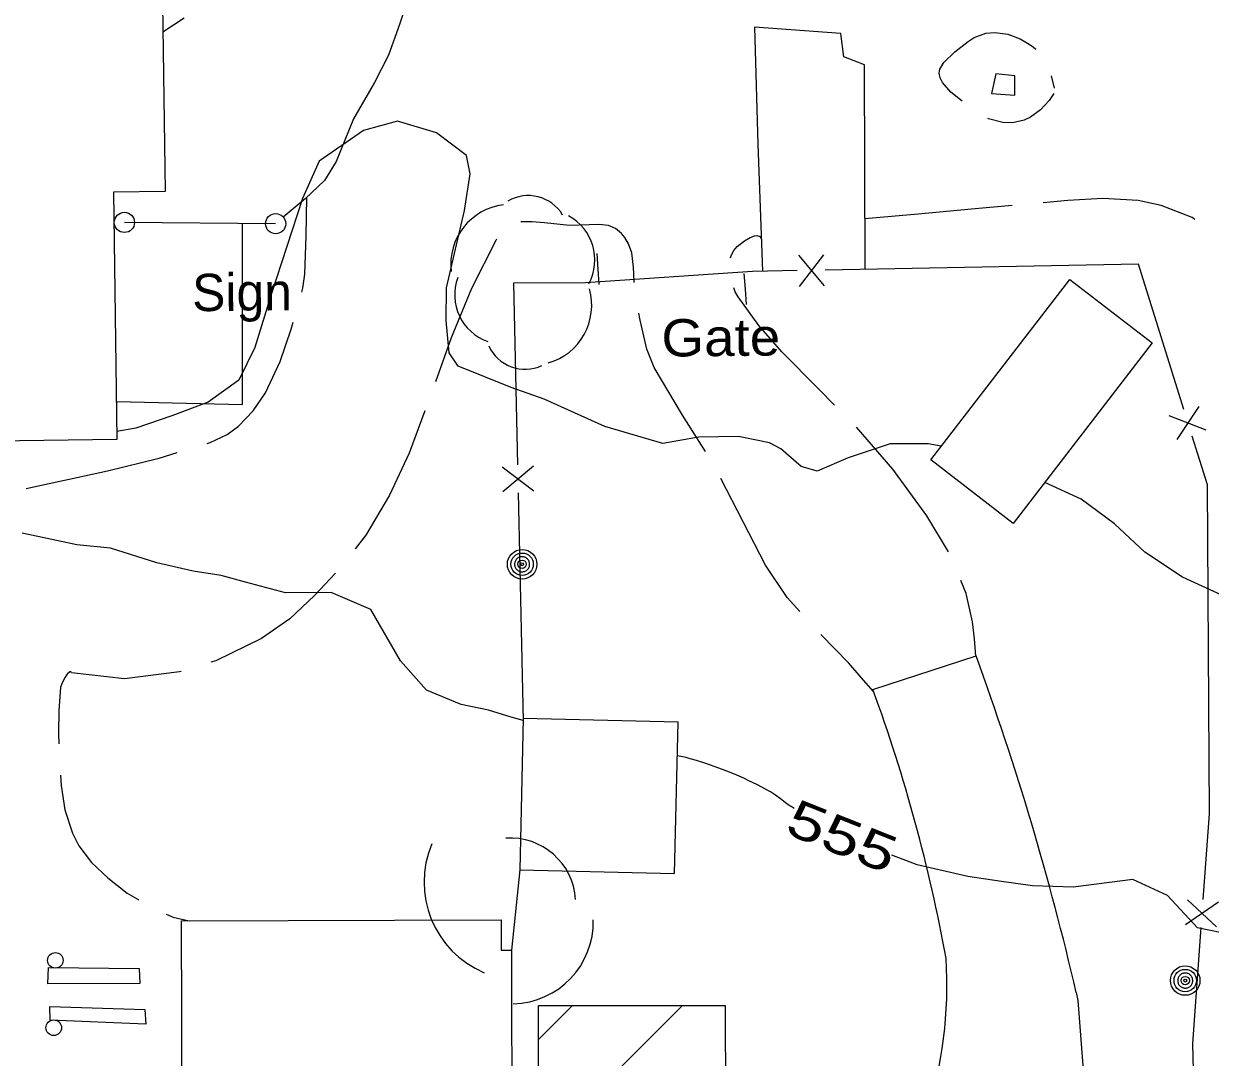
# Model space of a CAD drawing. Extents: x 2361284 to 2366480, y 6976556 to 6985346.
# Drawn here: x 2364468 to 2364620.8, y 6980286.6 to 6980419.7 of the extents above; entities that cross this region are included whole.
import ezdxf
from ezdxf.enums import TextEntityAlignment as Align

# ---------------------------------------------------------------- set-up
doc = ezdxf.new("R2010")
doc.units = 0
doc.header["$LTSCALE"] = 1.9
for name, color, linetype, lineweight in [('10', 7, 'Continuous', 13), ('11', 7, 'Continuous', 13), ('12', 7, 'Continuous', 13), ('13', 7, 'Continuous', 13), ('15', 7, 'Continuous', 13), ('16', 7, 'Continuous', 13), ('3', 7, 'Continuous', 13), ('4', 7, 'Continuous', 13), ('5', 7, 'Continuous', 13), ('7', 7, 'Continuous', 13), ('9', 7, 'Continuous', 13)]:
    doc.layers.add(name, color=color, linetype=linetype, lineweight=lineweight)

msp = doc.modelspace()

# ---------------------------------------------------------------- linework, layer by layer
at = {"layer": '10'}
for points in [[(2364595.653, 6980412.994), (2364593.181, 6980413.281), (2364592.655, 6980410.735), (2364595.627, 6980410.504)], [(2364482.84, 6980298.035), (2364482.919, 6980296.086), (2364471.079, 6980296.063), (2364471.179, 6980298.154)], [(2364483.571, 6980292.752), (2364483.709, 6980290.853), (2364471.373, 6980291.356), (2364471.336, 6980293.146)]]:
    msp.add_lwpolyline(points, close=True, dxfattribs=at)
at = {"layer": '11'}
msp.add_line((2364500.42, 6980393.958), (2364480.937, 6980394.123), dxfattribs=at)
for centre in [(2364480.938, 6980394.124), (2364500.421, 6980393.959)]:
    msp.add_circle(centre, 1.3, dxfattribs=at)
at = {"layer": '12'}
for points in [[(2364532.31, 6980329.987), (2364530.766, 6980330.412), (2364527.847, 6980331.325), (2364524.33, 6980332.021), (2364519.861, 6980333.9), (2364516.495, 6980337.638), (2364512.672, 6980344.282), (2364507.561, 6980346.443), (2364501.682, 6980346.437), (2364496.558, 6980347.788), (2364493.39, 6980348.638), (2364489.774, 6980349.224), (2364485.134, 6980350.269), (2364479.135, 6980352.183), (2364474.801, 6980352.611), (2364467.767, 6980354.095)], [(2364567.209, 6980318.648), (2364566.831, 6980318.88), (2364566.584, 6980319.044), (2364566.102, 6980319.387), (2364565.627, 6980319.741), (2364564.993, 6980320.213), (2364564.67, 6980320.442), (2364564.173, 6980320.766), (2364563.917, 6980320.917), (2364563.056, 6980321.388), (2364562.476, 6980321.689), (2364561.306, 6980322.262), (2364560.715, 6980322.534), (2364559.521, 6980323.053), (2364558.313, 6980323.541), (2364557.499, 6980323.851), (2364555.854, 6980324.441), (2364555.45, 6980324.577), (2364554.642, 6980324.828), (2364553.829, 6980325.053), (2364553.283, 6980325.191), (2364552.174, 6980325.436)], [(2364623.777, 6980302.325), (2364619.168, 6980303.252), (2364615.319, 6980307.415), (2364610.849, 6980309.503), (2364603.177, 6980308.52), (2364597.935, 6980308.67), (2364593.91, 6980309.252), (2364589.605, 6980309.861), (2364583.039, 6980311.4), (2364579.807, 6980312.629)]]:
    msp.add_lwpolyline(points, dxfattribs=at)
at = {"layer": '13'}
for points in [[(2364485.894, 6980418.671), (2364488.627, 6980420.467)], [(2364586.167, 6980365.302), (2364584.493, 6980365.616), (2364579.573, 6980365.619), (2364574.15, 6980363.807), (2364570.166, 6980362.099), (2364568.125, 6980362.679), (2364565.483, 6980364.97), (2364564.05, 6980365.731), (2364560.024, 6980366.533), (2364554.894, 6980366.464), (2364550.282, 6980365.631), (2364542.839, 6980367.84), (2364535.026, 6980371.346), (2364530.762, 6980372.855), (2364523.946, 6980375.62), (2364522.768, 6980377.335), (2364522.4, 6980381.506), (2364522.45, 6980385.707), (2364524.765, 6980395.649), (2364525.478, 6980400.39), (2364524.988, 6980402.732), (2364521.12, 6980405.645), (2364516.124, 6980407.178), (2364511.725, 6980405.976), (2364506.013, 6980401.991), (2364503.859, 6980397.211), (2364499.837, 6980384.832), (2364497.731, 6980378.011), (2364495.691, 6980373.811), (2364491.737, 6980370.994), (2364487.054, 6980369.2), (2364482.389, 6980367.645), (2364479.973, 6980367.212)], [(2364622.311, 6980346.104), (2364617.259, 6980348.426), (2364612.398, 6980351.67), (2364608.483, 6980355.303), (2364604.192, 6980358.473), (2364599.492, 6980360.628)]]:
    msp.add_lwpolyline(points, dxfattribs=at)
at = {"layer": '15'}
msp.add_line((2364600.304, 6980412.998), (2364600.699, 6980411.412), dxfattribs=at)
for points in [[(2364588.865, 6980409.749), (2364587.403, 6980410.906), (2364586.321, 6980412.125), (2364586.006, 6980412.732), (2364585.89, 6980413.341), (2364585.975, 6980413.852), (2364586.497, 6980414.737), (2364587.895, 6980416.08), (2364589.611, 6980417.417), (2364590.416, 6980417.945), (2364591.911, 6980418.479), (2364593.05, 6980418.59), (2364594.732, 6980418.366), (2364596.308, 6980417.771), (2364597.293, 6980417.23), (2364597.988, 6980416.756), (2364598.361, 6980416.42)], [(2364600.685, 6980410.712), (2364600.064, 6980409.806), (2364598.945, 6980408.625), (2364597.654, 6980407.693), (2364596.858, 6980407.305), (2364595.321, 6980406.971), (2364594.101, 6980406.989), (2364592.236, 6980407.471), (2364592.165, 6980407.511)], [(2364503.814, 6980385.12), (2364503.939, 6980385.641), (2364504.172, 6980387.443), (2364504.355, 6980392.385), (2364504.438, 6980397.336)], [(2364618.83, 6980394.514), (2364618.478, 6980394.75), (2364614.504, 6980396.313), (2364611.508, 6980396.934), (2364606.994, 6980397.191), (2364602.476, 6980396.938), (2364599.289, 6980396.648)], [(2364595.302, 6980396.29), (2364590.067, 6980395.82), (2364583.202, 6980395.205), (2364576.328, 6980394.6)], [(2364546.604, 6980386.397), (2364546.593, 6980386.526), (2364546.535, 6980388.366), (2364546.288, 6980390.204), (2364545.867, 6980391.35), (2364545.399, 6980392.165), (2364544.964, 6980392.711), (2364544.198, 6980393.354), (2364543.284, 6980393.715), (2364542.032, 6980393.843), (2364538.283, 6980393.708), (2364535.06, 6980394.057), (2364533.458, 6980394.212), (2364531.989, 6980394.218)], [(2364559.024, 6980389.575), (2364559.131, 6980389.966), (2364559.436, 6980390.519), (2364559.861, 6980391.003), (2364560.804, 6980391.772), (2364561.559, 6980392.199), (2364562.087, 6980392.384), (2364562.427, 6980392.427), (2364562.818, 6980392.311), (2364562.991, 6980391.933)], [(2364528.891, 6980391.948), (2364528.792, 6980391.797), (2364525.651, 6980385.597), (2364523.041, 6980379.262), (2364521.014, 6980373.592)], [(2364572.426, 6980370.591), (2364570.356, 6980372.682), (2364565.61, 6980377.467), (2364562.677, 6980380.849), (2364559.982, 6980384.534), (2364559.616, 6980385.18), (2364559.432, 6980385.678)], [(2364555.802, 6980364.603), (2364552.837, 6980369.285), (2364549.179, 6980375.43), (2364548.226, 6980377.812), (2364547.38, 6980381.544), (2364547.222, 6980382.442)], [(2364491.578, 6980365.642), (2364491.997, 6980365.766), (2364494.157, 6980366.817), (2364495.617, 6980367.881), (2364497.538, 6980369.849), (2364499.097, 6980372.154), (2364500.999, 6980376.191), (2364502.409, 6980380.366), (2364502.691, 6980381.279)], [(2364519.639, 6980369.839), (2364517.641, 6980364.42), (2364515.092, 6980359.006), (2364512.021, 6980353.825), (2364510.668, 6980352.062)], [(2364587.106, 6980351.699), (2364584.312, 6980356.344), (2364579.904, 6980362.332), (2364575.233, 6980367.738)], [(2364468.302, 6980359.841), (2364478.741, 6980362.15), (2364485.406, 6980363.764), (2364487.749, 6980364.476)], [(2364567.948, 6980343.998), (2364566.301, 6980345.811), (2364563.54, 6980349.985), (2364557.765, 6980361.122)], [(2364508.147, 6980348.958), (2364505.446, 6980346.052), (2364502.244, 6980343.083), (2364498.597, 6980340.538), (2364492.694, 6980337.672), (2364492.066, 6980337.476)], [(2364590.614, 6980338.273), (2364590.443, 6980340.491), (2364590.182, 6980342.699), (2364589.378, 6980346.31), (2364588.672, 6980348.024)], [(2364577.446, 6980333.717), (2364575.859, 6980335.532), (2364574.252, 6980337.337), (2364570.646, 6980341.043)], [(2364474.128, 6980336.095), (2364474.047, 6980336.264), (2364473.917, 6980336.253), (2364473.58, 6980335.93), (2364473.293, 6980335.537), (2364472.92, 6980334.834), (2364472.716, 6980334.212), (2364472.474, 6980331.248), (2364472.452, 6980328.278), (2364472.505, 6980326.948)], [(2364488.247, 6980336.289), (2364488.028, 6980336.227), (2364480.956, 6980335.33), (2364474.128, 6980336.095)], [(2364472.703, 6980322.95), (2364472.786, 6980321.581), (2364473.276, 6980318.485), (2364474.234, 6980315.455), (2364475.06, 6980313.813), (2364476.71, 6980311.679), (2364478.799, 6980309.707), (2364481.298, 6980307.731), (2364482.777, 6980306.855)], [(2364486.314, 6980305.009), (2364487.218, 6980304.657), (2364489.292, 6980304.177)]]:
    msp.add_lwpolyline(points, dxfattribs=at)
at = {"layer": '16'}
for centre, radius, start, end in [((2364532.968, 6980392.432), 5.15, 30.85983, 120.85983), ((2364530.699, 6980388.715), 7.729, 96.85071, 186.85071), ((2364535.097, 6980389.292), 6.444, 331.6668, 61.6668), ((2364529.933, 6980384.824), 6.444, 160.03592, 250.03592), ((2364533.409, 6980383.451), 7.729, 285.98261, 15.98261), ((2364532.561, 6980380.359), 5.15, 204.58182, 294.58182), ((2364530.637, 6980306.384), 8.449, 3.76416, 93.76416), ((2364532.22, 6980309.173), 12.681, 157.1296, 247.1296), ((2364530.769, 6980304.054), 10.572, 271.36296, 1.36296)]:
    msp.add_arc(centre, radius, start, end, dxfattribs=at)
at = {"layer": '3'}
for points in [[(2364524.216, 6980458.717), (2364523.72, 6980456.163), (2364522.845, 6980450.405), (2364521.533, 6980442.141), (2364519.439, 6980429.78), (2364517.678, 6980423.584), (2364516.386, 6980419.611), (2364514.944, 6980415.657), (2364513.137, 6980412.15), (2364510.461, 6980407.464), (2364508.213, 6980401.982), (2364506.727, 6980399.508), (2364504.24, 6980397.154), (2364501.392, 6980394.807)], [(2364576.35, 6980388.079), (2364576.279, 6980414.44), (2364573.609, 6980415.455), (2364573.221, 6980418.451), (2364562.091, 6980419.285), (2364562.525, 6980404.199), (2364563.15, 6980387.824)], [(2364479.916, 6980371.072), (2364496.15, 6980370.686), (2364496.139, 6980393.997)], [(2364577.364, 6980333.946), (2364577.364, 6980333.947), (2364590.644, 6980338.283), (2364590.644, 6980338.283)], [(2364603.556, 6980294.923), (2364603.766, 6980293.915), (2364606.46, 6980258.809), (2364597.591, 6980220.752), (2364582.102, 6980187.993), (2364563.55, 6980139.785), (2364555.874, 6980115.1), (2364550.217, 6980116.847), (2364550.217, 6980116.846)]]:
    msp.add_lwpolyline(points, dxfattribs=at)
for centre, radius, start, end in [((2364532.57, 6980295.02), 179.88, 21.07659, 62.51442), ((2364246.504, 6980212.191), 366.512, 13.04562, 20.12261), ((2364378.247, 6980261.13), 212.014, 10.3757, 20.08725), ((2364531.362, 6980295.938), 55.535, 342.16442, 3.48525)]:
    msp.add_arc(centre, radius, start, end, dxfattribs=at)
at = {"layer": '4'}
for centre, radius in [((2364532.169, 6980350.097), 1.9), ((2364532.169, 6980350.097), 1.442), ((2364532.169, 6980350.097), 0.539), ((2364532.169, 6980350.097), 0.192), ((2364472.043, 6980299.083), 1), ((2364617.593, 6980296.476), 1.9), ((2364617.593, 6980296.476), 1.442), ((2364617.593, 6980296.476), 0.539), ((2364617.593, 6980296.476), 0.192), ((2364471.835, 6980290.4), 1)]:
    msp.add_circle(centre, radius, dxfattribs=at)
for centre, start, end in [((2364532.169, 6980350.097), 174.71552, 185.96556), ((2364532.169, 6980350.097), 163.46611, 174.71615), ((2364532.169, 6980350.097), 185.96287, 197.21291), ((2364532.169, 6980350.097), 152.21535, 163.46538), ((2364532.169, 6980350.097), 197.21479, 208.46483), ((2364532.169, 6980350.097), 140.96646, 152.21649), ((2364532.169, 6980350.097), 208.46822, 219.71826), ((2364532.169, 6980350.097), 129.71376, 140.96379), ((2364532.169, 6980350.097), 118.46406, 129.71409), ((2364532.169, 6980350.097), 107.21593, 118.46597), ((2364532.169, 6980350.097), 95.96582, 107.21585), ((2364532.169, 6980350.097), 84.71553, 95.96557), ((2364532.169, 6980350.097), 73.46552, 84.71555), ((2364532.169, 6980350.097), 62.21535, 73.46538), ((2364532.169, 6980350.097), 50.96397, 62.214), ((2364532.169, 6980350.097), 39.71588, 50.96591), ((2364532.169, 6980350.097), 28.46656, 39.7166), ((2364532.169, 6980350.097), 320.96646, 332.21649), ((2364532.169, 6980350.097), 17.21479, 28.46483), ((2364532.169, 6980350.097), 332.21419, 343.46422), ((2364532.169, 6980350.097), 5.96345, 17.21348), ((2364532.169, 6980350.097), 343.46611, 354.71615), ((2364532.169, 6980350.097), 354.71553, 5.96557), ((2364532.169, 6980350.097), 219.71376, 230.96379), ((2364532.169, 6980350.097), 230.96397, 242.214), ((2364532.169, 6980350.097), 242.21812, 253.46815), ((2364532.169, 6980350.097), 253.46258, 264.71261), ((2364532.169, 6980350.097), 264.71553, 275.96557), ((2364532.169, 6980350.097), 275.96582, 287.21585), ((2364532.169, 6980350.097), 287.21593, 298.46597), ((2364532.169, 6980350.097), 298.46406, 309.71409), ((2364532.169, 6980350.097), 309.71589, 320.96592), ((2364617.593, 6980296.476), 174.71552, 185.96556), ((2364617.593, 6980296.476), 163.46611, 174.71615), ((2364617.593, 6980296.476), 185.96287, 197.21291), ((2364617.593, 6980296.476), 152.21535, 163.46538), ((2364617.593, 6980296.476), 197.21479, 208.46483), ((2364617.593, 6980296.476), 140.96646, 152.21649), ((2364617.593, 6980296.476), 129.71376, 140.96379), ((2364617.593, 6980296.476), 118.46406, 129.71409), ((2364617.593, 6980296.476), 107.21593, 118.46597), ((2364617.593, 6980296.476), 95.96582, 107.21585), ((2364617.593, 6980296.476), 84.71553, 95.96557), ((2364617.593, 6980296.476), 73.46552, 84.71555), ((2364617.593, 6980296.476), 62.21535, 73.46538), ((2364617.593, 6980296.476), 50.96397, 62.214), ((2364617.593, 6980296.476), 39.71588, 50.96591), ((2364617.593, 6980296.476), 28.46656, 39.7166), ((2364617.593, 6980296.476), 17.21479, 28.46483), ((2364617.593, 6980296.476), 332.21419, 343.46422), ((2364617.593, 6980296.476), 5.96345, 17.21348), ((2364617.593, 6980296.476), 343.46611, 354.71615), ((2364617.593, 6980296.476), 354.71553, 5.96557), ((2364617.593, 6980296.476), 208.46822, 219.71826), ((2364617.593, 6980296.476), 219.71376, 230.96379), ((2364617.593, 6980296.476), 230.96397, 242.214), ((2364617.593, 6980296.476), 242.21812, 253.46815), ((2364617.593, 6980296.476), 253.46258, 264.71261), ((2364617.593, 6980296.476), 264.71553, 275.96557), ((2364617.593, 6980296.476), 275.96582, 287.21585), ((2364617.593, 6980296.476), 287.21593, 298.46597), ((2364617.593, 6980296.476), 298.46406, 309.71409), ((2364617.593, 6980296.476), 309.71589, 320.96592), ((2364617.593, 6980296.476), 320.96646, 332.21649)]:
    msp.add_arc(centre, 0.973, start, end, dxfattribs=at)
at = {"layer": '5'}
for points in [[(2364542.084, 6980386.135), (2364541.964, 6980388.121), (2364541.844, 6980390.118)], [(2364560.752, 6980387.532), (2364560.901, 6980385.548), (2364561.05, 6980383.553)]]:
    msp.add_lwpolyline(points, dxfattribs=at)
at = {"layer": '7', "lineweight": 25}
for p, q in [((2364534.301, 6980288.887), (2364538.672, 6980293.257)), ((2364534.312, 6980274.756), (2364552.826, 6980293.269))]:
    msp.add_line(p, q, dxfattribs=at)
at = {"layer": '7'}
for points in [[(2364479.982, 6980366.172), (2364442.326, 6980365.664), (2364441.893, 6980397.511), (2364437.073, 6980397.446), (2364436.656, 6980427.594), (2364485.762, 6980428.271), (2364486.179, 6980398.113), (2364479.53, 6980398.019)], [(2364613.342, 6980378.601), (2364595.431, 6980355.359), (2364584.813, 6980363.549), (2364602.733, 6980386.78)], [(2364552.273, 6980329.747), (2364532.318, 6980330.217), (2364531.863, 6980310.752), (2364551.818, 6980310.282)]]:
    msp.add_lwpolyline(points, close=True, dxfattribs=at)
for points in [[(2364488.461, 6980253.867), (2364488.302, 6980304.178), (2364529.474, 6980304.309), (2364529.491, 6980300.399), (2364530.801, 6980300.401), (2364530.891, 6980250.95)], [(2364534.331, 6980250.953), (2364534.298, 6980293.254), (2364558.34, 6980293.273), (2364558.354, 6980281.263)]]:
    msp.add_lwpolyline(points, dxfattribs=at)
at = {"layer": '9'}
for p, q in [((2364567.782, 6980389.888), (2364571.06, 6980385.949)), ((2364570.981, 6980389.948), (2364567.86, 6980385.889)), ((2364619.359, 6980370.428), (2364616.491, 6980366.18)), ((2364620.308, 6980367.366), (2364615.541, 6980369.231)), ((2364529.619, 6980362.664), (2364533.688, 6980359.553)), ((2364529.689, 6980359.465), (2364533.617, 6980362.752)), ((2364531.661, 6980359.303), (2364532.31, 6980329.937)), ((2364531.863, 6980310.752), (2364530.801, 6980300.401)), ((2364621.627, 6980303.385), (2364617.875, 6980306.86)), ((2364621.856, 6980306.577), (2364617.645, 6980303.667)), ((2364618.569, 6980288.365), (2364619.647, 6980303.326)), ((2364619.112, 6980267.05), (2364618.569, 6980288.365))]:
    msp.add_line(p, q, dxfattribs=at)
for points in [[(2364567.611, 6980387.916), (2364561.85, 6980387.802), (2364540.323, 6980386.337), (2364531.064, 6980386.299), (2364531.577, 6980362.903)], [(2364617.413, 6980370.029), (2364611.586, 6980388.764), (2364571.21, 6980387.981)], [(2364619.903, 6980306.919), (2364620.708, 6980317.967), (2364620.446, 6980360.307), (2364618.486, 6980366.589)]]:
    msp.add_lwpolyline(points, dxfattribs=at)

# ---------------------------------------------------------------- texts
at = {"layer": '11'}
msp.add_text('Sign', height=4.799, rotation=0.545, dxfattribs=at).set_placement((2364489.686, 6980382.685))
at = {"layer": '12', "width": 1.35}
msp.add_text(' 555 ', height=4.8, rotation=338.353, dxfattribs=at).set_placement((2364572.535, 6980312.845), align=Align.CENTER)
at = {"layer": '9', "width": 1.1}
msp.add_text('Gate', height=4.799, rotation=0.545, dxfattribs=at).set_placement((2364550.135, 6980376.839))

doc.saveas('drawing.dxf')
